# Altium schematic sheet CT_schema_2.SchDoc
size 271 x 229 mm
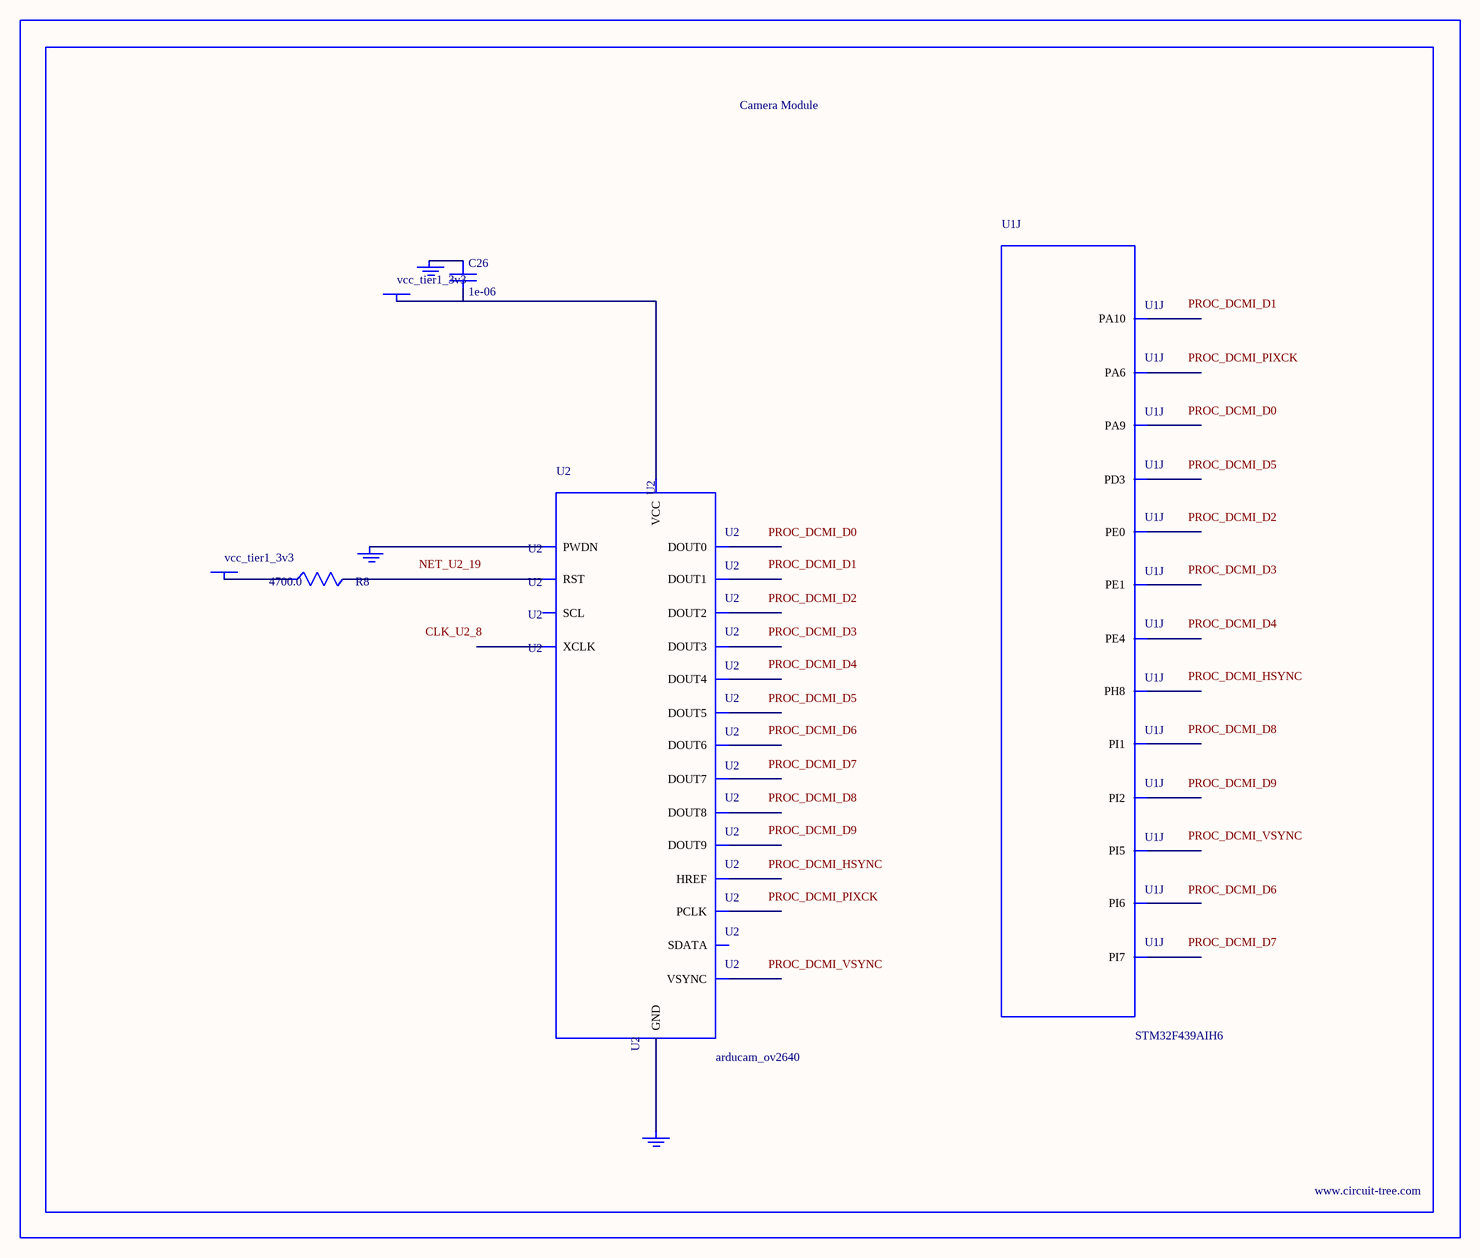
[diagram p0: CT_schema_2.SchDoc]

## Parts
BORDER1  (no value)
C26  1e-06  [C0603]
GND_INSTANCE_1_0  (no value)
GND_INSTANCE_1_1  (no value)
GND_INSTANCE_1_2  (no value)
POWER_INSTANCE_1_0  vcc_tier1_3v3
POWER_INSTANCE_1_1  vcc_tier1_3v3
R8  4700.0  [R0603]
U1  STM32F439AIH6  [UFBGA169]  (part J of 12)
U2  arducam_ov2640  [ARDUCAM]

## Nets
NetC26_1: C26.1 GND_INSTANCE_1_0.0(GND)
NetC26_2: C26.2 POWER_INSTANCE_1_0.0(PWR) U2.1(VCC)
NetGND_INSTANCE_1_1_0: GND_INSTANCE_1_1.0(GND) U2.20(PWDN)
NetGND_INSTANCE_1_2_0: GND_INSTANCE_1_2.0(GND) U2.2(GND)
NetPOWER_INSTANCE_1_1_0: POWER_INSTANCE_1_1.0(PWR) R8.1
NetR8_2: R8.2 U2.19(RST)

Not connected (* = marked no-connect by the designer): U1 A2(PI6) A3(PI5) A4(PE1) A9(PD3) B1(PI7) B4(PE0) B12(PI2) C2(PE4) C11(PI1) E8(PA9) E9(PA10) L10(PH8) N3(PA6); U2 3(SCL) 4(SDATA) 5(VSYNC) 6(HREF) 7(PCLK) 8(XCLK) 9(DOUT9) 10(DOUT8) 11(DOUT7) 12(DOUT6) 13(DOUT5) 14(DOUT4) 15(DOUT3) 16(DOUT2) 17(DOUT1) 18(DOUT0)

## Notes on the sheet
- Labels drawn without touching a wire or pin: CLK_U2_8, NET_U2_19, PROC_DCMI_D0, PROC_DCMI_D1, PROC_DCMI_D2, PROC_DCMI_D3, PROC_DCMI_D4, PROC_DCMI_D5, PROC_DCMI_D6, PROC_DCMI_D7, PROC_DCMI_D8, PROC_DCMI_D9, PROC_DCMI_HSYNC, PROC_DCMI_PIXCK, PROC_DCMI_VSYNC

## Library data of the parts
BORDER1 = BORDER_PAGE1
C26 = C0603C105K3RACTU
GND_INSTANCE_1_0-GND_INSTANCE_1_2 = GND
POWER_INSTANCE_1_0 POWER_INSTANCE_1_1 = PWR
R8 = RC0603JR-074K7L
